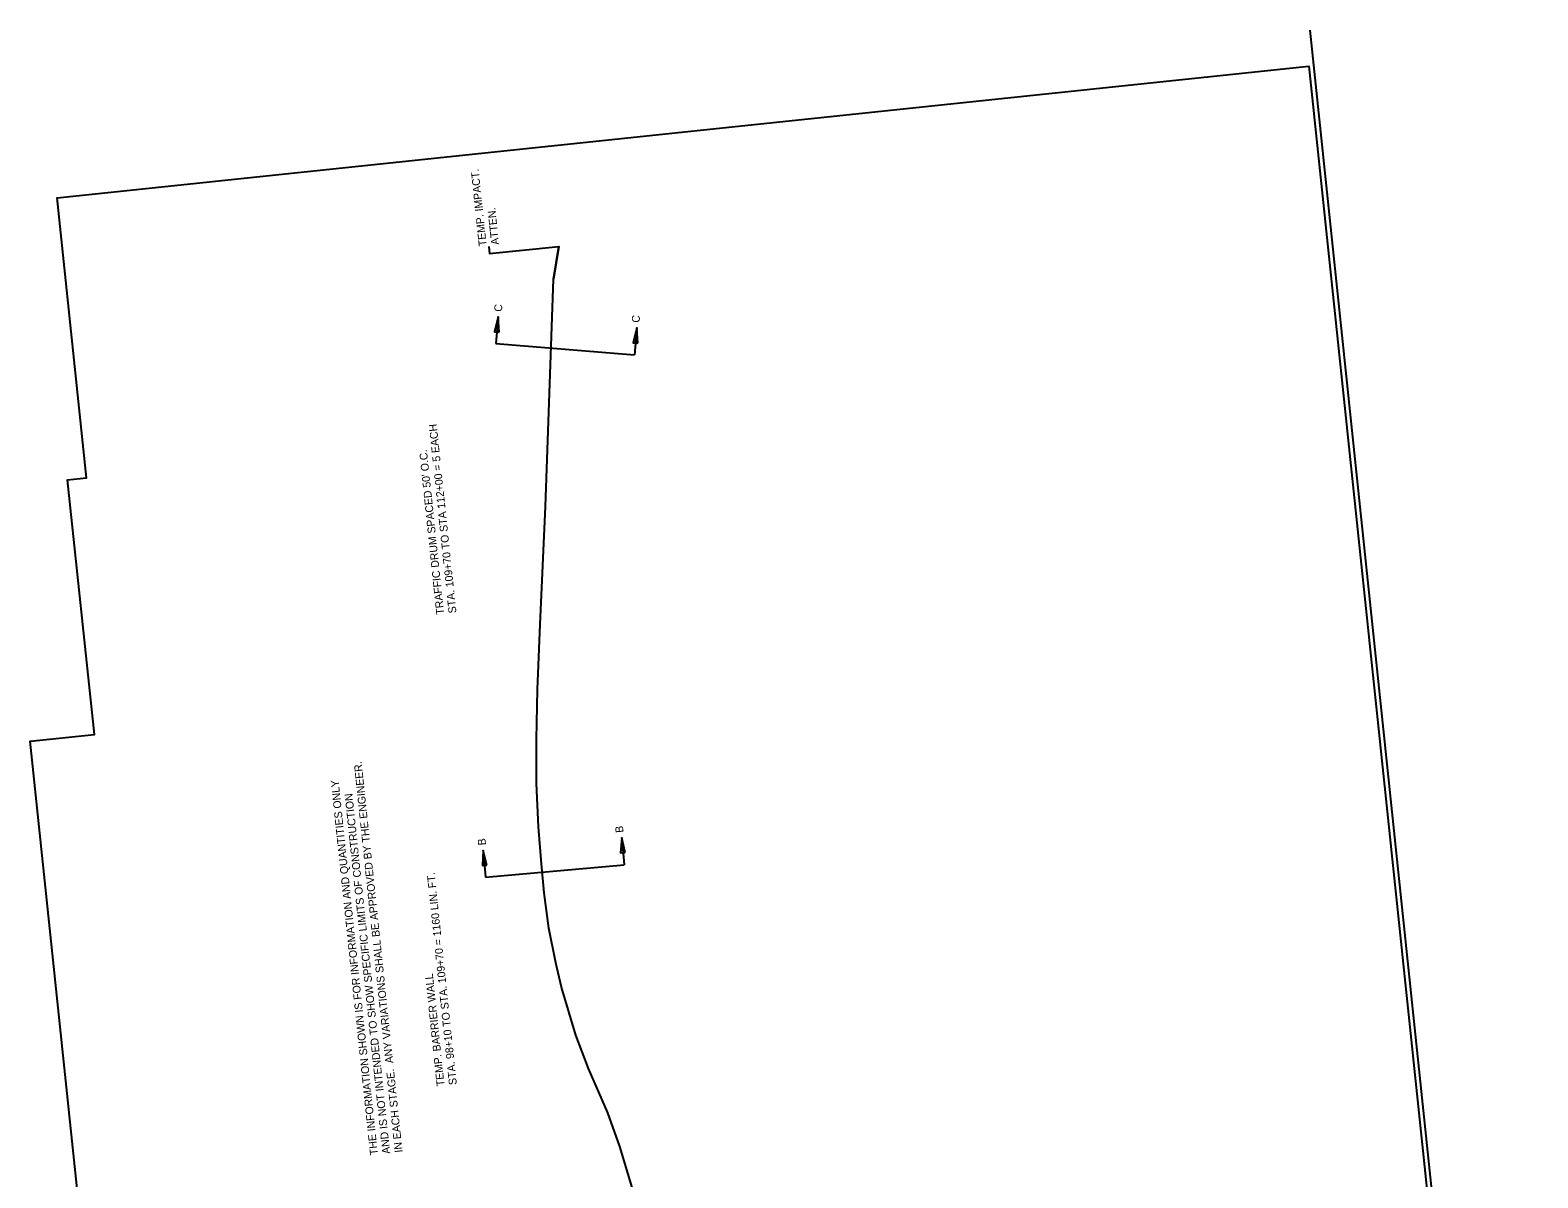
# Model space of a CAD drawing. Extents: x 633427 to 634998, y 288285 to 294065.
# Drawn here: x 633427 to 634580, y 293187 to 294065 of the extents above; entities that cross this region are included whole.
import ezdxf

# ---------------------------------------------------------------- set-up
doc = ezdxf.new("R2010")
doc.units = 0
for name, color, linetype in [('Default', 7, 'Continuous'), ('R_50 Horz Alg Ticks', 7, 'Continuous'), ('R_Vert Alg Annot', 7, 'Continuous'), ('S_BASELINE', 7, 'Continuous'), ('S_BRIDGE', 7, 'Continuous')]:
    doc.layers.add(name, color=color, linetype=linetype)

msp = doc.modelspace()

# ---------------------------------------------------------------- linework, layer by layer
at = {"layer": 'Default'}
for p, q in [((633784.7, 293845.4), (633783, 293824.9)), ((633890.7, 293837), (633889, 293816.2)), ((633783, 293824.9), (633889, 293816.2)), ((633773.3, 293437.2), (633775.1, 293416.7)), ((633879.2, 293446.9), (633881, 293426.1)), ((633775.1, 293416.7), (633881, 293426.1))]:
    msp.add_line(p, q, dxfattribs=at)
at = {"layer": 'R_50 Horz Alg Ticks'}
for points in [[(633785.5, 293833.7), (633784.7, 293845.4), (633782, 293834)], [(633891.5, 293825.3), (633890.7, 293837), (633888, 293825.6)], [(633776.1, 293425.8), (633773.3, 293437.2), (633772.6, 293425.5)], [(633881.9, 293435.5), (633879.2, 293446.9), (633878.4, 293435.2)]]:
    msp.add_lwpolyline(points, close=True, dxfattribs=at)
at = {"layer": 'R_Vert Alg Annot'}
for points in [[(633777.5, 293899.3), (633778.1, 293893.8), (633831.1, 293899.2)], [(633827, 293874.2), (633831.1, 293899.2), (633827, 293874.2)], [(634015.4, 292805.9), (633887.2, 293179.3), (633877.7, 293210.7), (633868.5, 293236.5), (633853.8, 293270.4), (633844.2, 293295.9), (633833.2, 293332.4), (633828.8, 293351.2), (633823.5, 293377.7), (633820, 293404.7), (633817.8, 293427), (633815.6, 293455.1), (633814.1, 293488.3), (633813.9, 293522), (633814.8, 293560.2), (633816.8, 293610.1), (633820.8, 293700.4), (633824, 293787), (633827, 293874.2)]]:
    msp.add_lwpolyline(points, dxfattribs=at)
at = {"layer": 'S_BASELINE'}
msp.add_lwpolyline([(634572.3, 292445.3), (633550.9, 292338), (633426.6, 293520.7), (633475.7, 293525.9), (633455.2, 293720.6), (633469.8, 293722.1), (633447.2, 293936.5), (634405, 294037.1)], close=True, dxfattribs=at)
at = {"layer": 'S_BRIDGE'}
msp.add_line((634580.2, 292406.6), (634405.9, 294064.7), dxfattribs=at)

# ---------------------------------------------------------------- texts
at = {"layer": 'R_50 Horz Alg Ticks'}
for s, rotation, p in [('C', 85.2982, (633787.5, 293849.1)), ('C', 85.2982, (633892.8, 293840.7)), ('B', 95.0468, (633880.6, 293450.9)), ('B', 95.0468, (633775.4, 293441.3))]:
    msp.add_text(s, height=6, rotation=rotation, dxfattribs=at).set_placement(p)
at = {"layer": 'R_Vert Alg Annot'}
for s, p in [('TEMP. IMPACT.', (633775.9, 293899.8)), ('ATTEN.', (633785.4, 293900.8)), ('STA. 109+70 TO STA 112+00 = 5 EACH', (633752.8, 293618.9)), ("TRAFFIC DRUM SPACED 50' O.C.", (633743.4, 293617.9)), ('IN EACH STAGE.  ANY VARIATIONS SHALL BE APPROVED BY THE ENGINEER.', (633711.6, 293206.3)), ('THE INFORMATION SHOWN IS FOR INFORMATION AND QUANTITIES ONLY', (633692.7, 293204.4)), ('AND IS NOT INTENDED TO SHOW SPECIFIC LIMITS OF CONSTRUCTION', (633702.1, 293205.3)), ('STA. 98+10 TO STA. 109+70 = 1160 LIN. FT.', (633753.1, 293258)), ('TEMP. BARRIER WALL', (633743.7, 293257.1))]:
    msp.add_text(s, height=6, rotation=96, dxfattribs=at).set_placement(p)

doc.saveas('drawing.dxf')
